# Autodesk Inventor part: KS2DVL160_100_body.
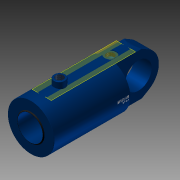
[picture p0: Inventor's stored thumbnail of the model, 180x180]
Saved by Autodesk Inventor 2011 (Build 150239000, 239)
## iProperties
Created: 2010-11
Document SubType Name: Modeling
Designer: TB
Mass: 405.061 g
Surface Area: 916.939 cm^2
Volume: 405.061 cm^3
Density: 1 g/cm^3
Author: TB
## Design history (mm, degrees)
sketch "Sketch2"
  geometry: L1 (-35, -3)-(-35, 3); L2 (-35, -9)-(-35, 9); L3 (-35, 0)-(-35, 92.5); L4 (-35, 92.5)-(-328, 92.5); L5 (-328, 92.5)-(-328, 92.5); L6 (-328, 92.5)-(-338, 92.5); L7 (-338, 92.5)-(-338, 54); L8 (-338, 54)-(-341, 51); L9 (-341, 51)-(-341, 50); L10 (-341, 50)-(-214, 50); L11 (-214, 50)-(-214, 80); L12 (-214, 80)-(-62, 80); L13 (-62, 80)-(-62, 0); L14 (-62, 0)-(-35, 0); L15 (-62, 0)-(-148.421, 0); L16 (-35, 9)-(-32, 12) reference; L17 (-32, 12)-(-35, 12) reference; L18 (-35, 12)-(-35, 9) reference; L19 (-32, 12)-(-35, 9) reference; L20 (-32, 12)-(-35, 12) reference; L21 (-35, 9)-(-35, 12) reference; L22 (-35, 9)-(-32, 12) reference; 1 further point
  constraints: 44 end point, 8 perpendicular, 6 parallel, 5 collinear, 2 horizontal, 2 vertical, 1 coincident, 1 midpoint, 1 point on line, 10 other
  dimensions: "DiaY" = 185 diameter of L4 L15; "DiaI" = 160 diameter of L12 L15; "d4" = 1 distance of L8.end L9.end; "d5" = 45 deg angle of L10 L8; "d6" = 3 distance between parallel lines of L7 L9; "DiaStang" = 100 diameter of L10 L15; "RindDia" = 185 diameter of L6 L15; "RingLengde" = 10 distance of L5.end L6.end; "RingTykk" = 124 distance between parallel lines of L11 L7; "KroppLengde" = 303 distance between parallel lines of L7 L3 (derived); "BunnTykkelse" = 27 distance between parallel lines of L13 L3
revolve "Kropp" sketch "Sketch2" stored, may be unused: angle "d13" = 90 deg
sketch "Sketch3"
  geometry: L1 (-62, -80)-(-62, 80) reference; L2 (-62, 0.01)-(-162, 0.01); L3 (-162, -0.01)-(-62, -0.01); A1 r 0.01 centre (-162, 0) between (-162, 0.01) and (-162, -0.01); A2 r 0.01 centre (-62, 0) between (-62, -0.01) and (-62, 0.01); 2 further points
  constraints: 4 end point, 4 point on circle, 4 tangent, 2 centre point, 1 coincident, 1 midpoint, 1 parallel, 1 perpendicular
  dimensions: "d17" = 0.01 radius of A2; "d18" = 100 distance of L2.start L2.end (= Slaglengde)
feature "BaneTransitionalConstraint" sketch "Sketch3" dims "d19" = 2, "d20" = 0
sketch "Sketch6"
  geometry: L1 (-129.5, 0)-(129.5, 0) reference; L2 (16.591, 91)-(-11.843, 91); L3 (92.5, 0)-(92.5, 31.248); L4 (-92.5, 0)-(-92.5, -18.451); A1 r 92.5 centre (0, 0) between (-92.5, 0) and (92.5, 0) reference; 2 further points
  constraints: 6 end point, 2 point on circle, 2 vertical, 2 other
  dimensions: "d30" = 91 distance from line of point (0, 0) L2 (computed from DiaY); "d31" = 0 deg angle of L1 L2 (computed from Vinkel_Plussport); "d37" = 90 deg angle of L2 L3; "d38" = 90 deg angle of L2 L4
  node "Projected Loop3"
workplane "Work Plane5"
sketch "Sketch7"
  geometry: L1 (16.591, -409.2)-(16.591, 68.2) reference; L2 (-19.633, -35)-(38.367, -35) reference; C1 r 22.5 at (16.591, -52.5); 1 further point
  constraints: 1 centre point, 1 point on line
  dimensions: "PortDia" = 45 diameter of C1
extrude "Extrusion2" cut sketch "Sketch7" stored distance "d34" = 1.5; taper "d35" = 0 deg
workplane "Work Plane7"
sketch "Sketch4"
  geometry: L1 (-16.68, -40)-(-16.68, -78.777); L2 (-16.68, -78.777)-(16.68, -78.777); L3 (16.68, -78.777)-(16.68, -40); L4 (16.68, -40)-(-16.68, -40); L5 (-40.643, -40)-(0, -40); L6 (-29, -35)-(29, -35); L7 (0, -35)-(0, -40); 2 further points
  constraints: 6 end point, 2 midpoint, 2 other
  dimensions: "d40" = 5 distance of L7.start L5.end
emboss "Emboss1" sketch "Sketch4" dims "d4" = 1, "d5" = 45 deg, "d6" = 3, "d22" = 0.2, "d23" = 0, "DiaI" = 160, "DiaY" = 185, "RindDia" = 185, "DiaStang" = 100, "RingTykk" = 124, "RingLengde" = 10, "KroppLengde" = 303 (derived), "BunnTykkelse" = 27
workplane "Work Plane8"
sketch "Sketch8"
  geometry: L1 (-29, -35)-(29, -35); L2 (0, -35)-(0, -40); L3 (-5.906, -110.587)-(-5.906, -40); L4 (-5.906, -40)-(5.906, -40); L5 (5.906, -40)-(5.906, -110.587); L6 (5.906, -110.587)-(-5.906, -110.587); L7 (92.5, -35)-(-92.5, -35); L8 (92.5, -35)-(-92.5, -35) reference; 3 further points
  constraints: 6 end point, 4 midpoint, 2 other
  dimensions: "d42" = 5 distance of L2.start L2.end
emboss "Emboss2" sketch "Sketch8" dims "d4" = 1, "d5" = 45 deg, "d6" = 3, "d43" = 0.2, "d44" = 0, "DiaI" = 160, "DiaY" = 185, "RindDia" = 185, "DiaStang" = 100, "RingTykk" = 124, "RingLengde" = 10, "KroppLengde" = 303 (derived), "BunnTykkelse" = 27
sketch "Sketch9"
  geometry: A1 r 12.5 centre (9.367, -52.5) between (0, -60.776) and (18.735, -60.776) reference; 1 further point
hole "Hole1" sketch "Sketch9" at (9.367, -52.5) diameter "d45" = 14.95; stored, may be unused: countersink angle "d49" = 82 deg, drill point angle "d51" = 118 deg; dims "d46" = 6, "d47" = 3.023, "d48" = 2, "DiaInvPluss" = 30.5
workplane "Work Plane9"
sketch "Sketch10"
  geometry: L1 (-129.5, 0)-(129.5, 0) reference; L2 (0, 92.5)-(13.136, 92.5); L3 (0, 92.5)-(0, 31.79); L4 (22.5, 89.722)-(22.5, 115.5); L5 (22.5, 115.5)-(0, 115.5); L6 (0, 115.5)-(0, 92.5); L7 (0, 92.5)-(22.5, 89.722); C1 r 92.5 at (0, 0) reference; A1 r 92.5 centre (0, 0) between (0, 92.5) and (22.5, 89.722); 1 further point
  constraints: 12 end point, 4 perpendicular, 2 concentric, 2 point on circle, 1 centre point, 1 point on line, 1 tangent
  dimensions: "d53" = 0 deg angle of L1 L2 (computed from Vinkel_Minusport); "DiaUtvStussMinus" = 45 diameter of L4 L3; "HøydeStussMinuss" = 23 distance between parallel lines of L2 L5
revolve "Revolution2" sketch "Sketch10" stored, may be unused: angle "d56" = 90 deg
hole "Hole2" diameter "d59" = 30.291; stored, may be unused: countersink angle "d63" = 82 deg, drill point angle "d65" = 118 deg; dims "d57" = 10, "d58" = 10, "d60" = 6, "d61" = 3.023, "d62" = 2, "DiaInvStussMinus" = 30.5
fillet "Fillet1" dims "d66" = 2
sketch "Sketch15"
  geometry: L1 (35, -85.623)-(35, 85.623); L2 (-35, -85.623)-(-35, 85.623); L3 (0, 129.5)-(0, -129.5) reference; A1 r 92.5 centre (0, 0) between (35, -85.623) and (-35, -85.623) reference; A2 r 92.5 centre (0, 0) between (35, 85.623) and (-35, 85.623); A3 r 92.5 centre (0, 0) between (-35, -85.623) and (35, -85.623)
  constraints: 8 point on circle, 4 end point, 4 point on line, 2 centre point, 2 concentric, 2 parallel, 1 coincident
  dimensions: "EyeBunnTykk" = 35 distance from line of L1 A1.centre; "EyeBunnTykk2" = 35 distance from line of A1.centre L2
extrude "Extrusion6" join sketch "Sketch15" taper "d98" = 0 deg; distance "LengdeEyeMinussBunntykk" = 170
sketch "Sketch16"
  geometry: L1 (-337, 92.5)-(135, 92.5) reference; L2 (-337, -92.5)-(135, -92.5) reference; L3 (-337, 92.5)-(135, 92.5) reference; L4 (135, 92.5)-(135, 85.623) reference; L5 (135, -85.623)-(135, 85.623) reference; L6 (-434.9, 0)-(250.401, 0) reference; L7 (50.5, 92.5)-(135, 92.5); L8 (135, 92.5)-(135, 8); A1 r 84.5 centre (50.5, 8) between (135, 8) and (50.5, 92.5); 6 further points; 2 other entities
  constraints: 4 end point, 4 tangent, 2 point on circle, 2 point on line, 1 centre point, 1 collinear, 1 perpendicular, 2 other
  dimensions: "d137" = 8 distance from line of L8.end L6
extrude "Extrusion7" cut sketch "Sketch16" taper "d102" = 0 deg; stored distance "ExtruEyeBunn" = 70
mirror "Mirror1"
sketch "Sketch20"
  geometry: L1 (-337, 92.5)-(135, 92.5) reference; L2 (135, -85.623)-(135, 85.623) reference; L3 (135, 92.5)-(135, 85.623) reference; L4 (-432.681, 0)-(237.083, 0) reference; L5 (-35, -85.623)-(-35, 85.623) reference; L6 (-35, 0)-(55, 0); L7 (55, 0)-(55, 20.918); L8 (62.747, 88.481)-(96, 69.282); A1 r 35 centre (43.843, 57.5) between (43.843, 92.5) and (43.843, 92.5); A2 r 30 centre (47.747, 62.5) between (62.747, 88.481) and (47.747, 92.5); A3 r 80 centre (56, 0) between (135, 12.61) and (96, 69.282); 2 further points
  constraints: 7 point on line, 6 end point, 6 point on circle, 3 centre point, 2 tangent, 1 midpoint, 1 perpendicular
  dimensions: "d147" = 90 distance of L6.start L6.end; "d165" = 80 radius of A3; "d166" = 30 deg angle of L1 L8; "d167" = 30 radius of A2; "d169" = 1 distance of L6.end A3.centre
extrude "Extrusion10" cut sketch "Sketch20" stored distance "d144" = 10; taper "d145" = 0 deg
mirror "Mirror2"
sketch "Sketch17"
  geometry: L1 (171.245, 0)-(0, 0) reference; L2 (85.623, -401.2)-(85.623, 265.2) reference; C1 r 52.5 at (85.623, 90); 1 further point
  constraints: 1 centre point, 1 point on line
  dimensions: "DiaHullEyeBunn" = 105 diameter of C1; "d125" = 90 distance from line of C1.centre L1
extrude "Extrusion8" cut sketch "Sketch17" taper "d105" = 0 deg; distance "ExtruHullEye" = 70
pattern_circular "Circular Pattern1 Only Subsea" dims "d108" = 180 deg (derived)
workplane "Work Plane11"
sketch "Sketch18"
  geometry: L1 (0, -74.5)-(0, 13) reference; L2 (80, -62)-(-80, -62) reference; L3 (80, -62)-(-80, -62) reference; C1 r 22.5 at (0, -22); 1 further point
  constraints: 1 centre point
  dimensions: "DiaForsenkPlussPort" = 45 diameter of C1; "PlassPlussport" = 40 distance from line of L2 C1.centre
extrude "Extrusion9" cut sketch "Sketch18" stored distance "d113" = 10; taper "d114" = 0 deg
sketch "Sketch19"
  geometry: 8 further points
  constraints: 1 other
hole "Hole3" sketch "Sketch19" at (0, -22) diameter "d115" = 30.291; stored, may be unused: countersink angle "d119" = 90 deg, drill point angle "d121" = 118 deg; dims "d116" = 6, "d117" = 4, "d118" = 2, "d120" = 14.5
pattern_circular "Circular Pattern2 Only Subsea" dims angle "d123" = 360 deg
body "Solid1"
chamfer "Chamfer" distance "Chamfer" = 1; stored, may be unused: second distance "d15" = 2, angle "d16" = 45 deg
node "Projected Loop2"
body "Srf1"
node "Projected Loop10"
other parameters: "Slaglengde" = 100, "Forlengelse_rør" = 0, "Vinkel_Plussport" = 0 [user parameter; used in 1 equation term], "Vinkel_Minusport" = 0, "d32" = 90 deg, "d39" = 90 deg, "d41" = 90 deg, "PortMinusPlass" = -114, "Minusport2" = 180 deg, "ForsenkningPlussPort" = 90.7 (derived), "EyeLengdeUBunn" = 136, "d164" = 73
